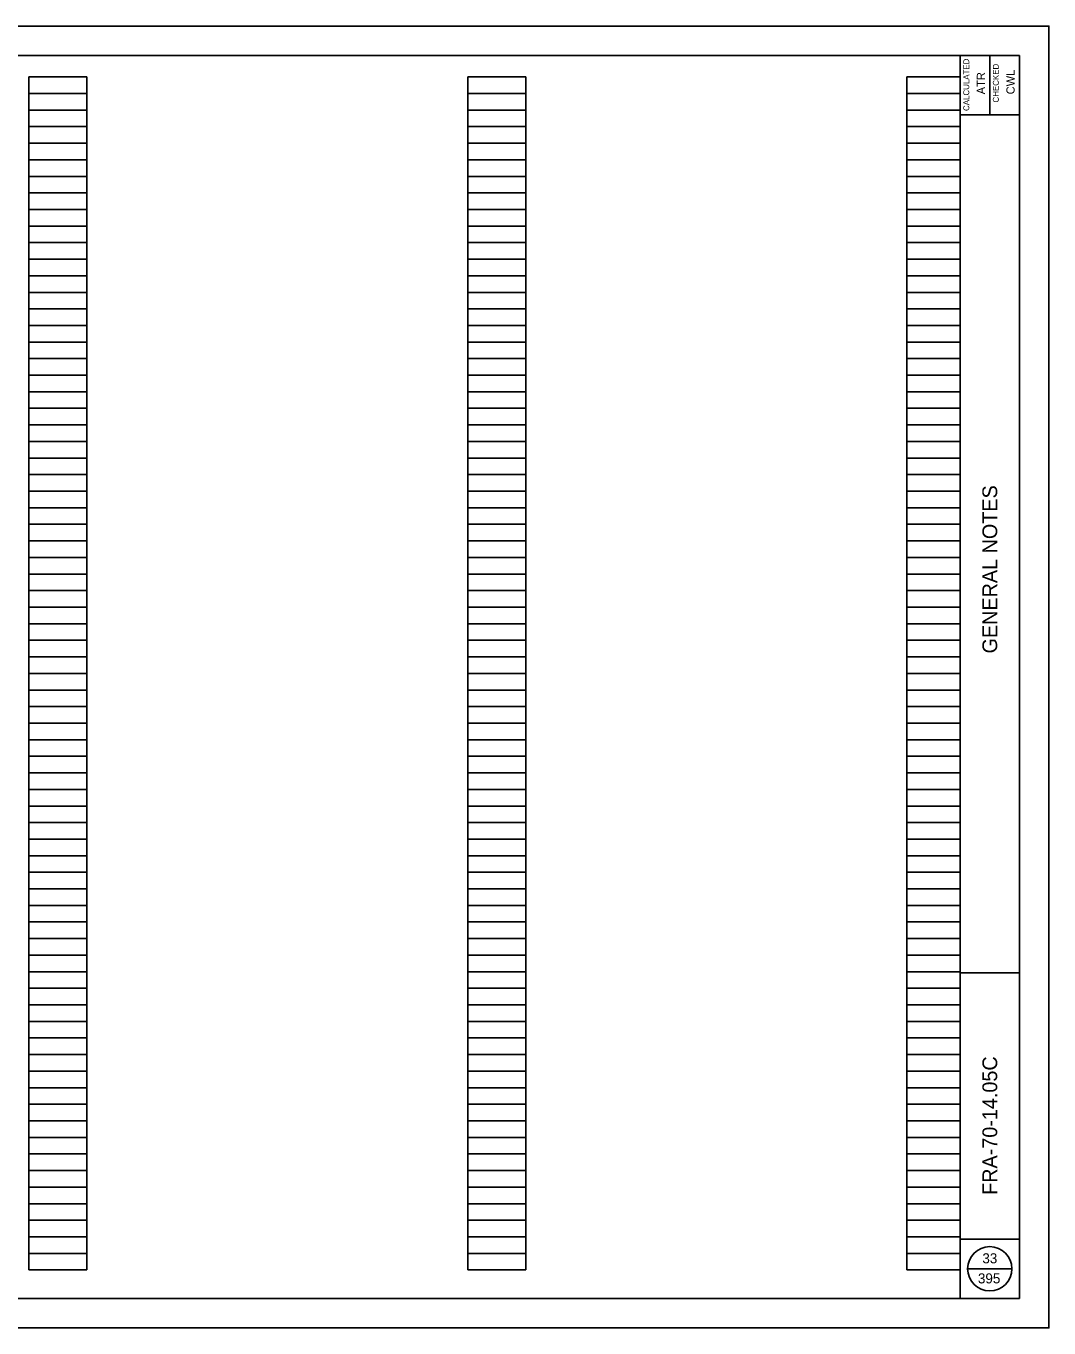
# Model space of a CAD drawing. Extents: x 0 to 34, y 0 to 22.
# Drawn here: x 16.71 to 34, y 0 to 22 of the extents above; entities that cross this region are included whole.
import ezdxf

# ---------------------------------------------------------------- set-up
doc = ezdxf.new("R2010")
doc.units = 0
for name, color, linetype in [('SC_Scratch1', 7, 'Continuous'), ('SH_Border', 7, 'Continuous'), ('SH_Cut_Line', 7, 'Continuous'), ('SH_Data', 7, 'Continuous')]:
    doc.layers.add(name, color=color, linetype=linetype)

msp = doc.modelspace()

# ---------------------------------------------------------------- linework, layer by layer
at = {"layer": 'SC_Scratch1'}
for p, q in [((16.76, 0.98), (16.76, 21.14)), ((16.76, 21.14), (17.74, 21.14)), ((17.74, 0.98), (17.74, 21.14)), ((24.18, 0.98), (24.18, 21.14)), ((24.18, 21.14), (25.16, 21.14)), ((25.16, 0.98), (25.16, 21.14)), ((31.6, 0.98), (31.6, 21.14)), ((31.6, 21.14), (32.5, 21.14)), ((32.5, 0.98), (32.5, 21.14)), ((16.76, 20.86), (17.74, 20.86)), ((24.18, 20.86), (25.16, 20.86)), ((31.6, 20.86), (32.5, 20.86)), ((16.76, 20.58), (17.74, 20.58)), ((24.18, 20.58), (25.16, 20.58)), ((31.6, 20.58), (32.5, 20.58)), ((16.76, 20.3), (17.74, 20.3)), ((24.18, 20.3), (25.16, 20.3)), ((31.6, 20.3), (32.5, 20.3)), ((16.76, 20.02), (17.74, 20.02)), ((24.18, 20.02), (25.16, 20.02)), ((31.6, 20.02), (32.5, 20.02)), ((16.76, 19.74), (17.74, 19.74)), ((24.18, 19.74), (25.16, 19.74)), ((31.6, 19.74), (32.5, 19.74)), ((16.76, 19.46), (17.74, 19.46)), ((24.18, 19.46), (25.16, 19.46)), ((31.6, 19.46), (32.5, 19.46)), ((16.76, 19.18), (17.74, 19.18)), ((24.18, 19.18), (25.16, 19.18)), ((31.6, 19.18), (32.5, 19.18)), ((16.76, 18.9), (17.74, 18.9)), ((24.18, 18.9), (25.16, 18.9)), ((31.6, 18.9), (32.5, 18.9)), ((16.76, 18.62), (17.74, 18.62)), ((24.18, 18.62), (25.16, 18.62)), ((31.6, 18.62), (32.5, 18.62)), ((16.76, 18.34), (17.74, 18.34)), ((24.18, 18.34), (25.16, 18.34)), ((31.6, 18.34), (32.5, 18.34)), ((16.76, 18.06), (17.74, 18.06)), ((24.18, 18.06), (25.16, 18.06)), ((31.6, 18.06), (32.5, 18.06)), ((16.76, 17.78), (17.74, 17.78)), ((24.18, 17.78), (25.16, 17.78)), ((31.6, 17.78), (32.5, 17.78)), ((16.76, 17.5), (17.74, 17.5)), ((24.18, 17.5), (25.16, 17.5)), ((31.6, 17.5), (32.5, 17.5)), ((16.76, 17.22), (17.74, 17.22)), ((24.18, 17.22), (25.16, 17.22)), ((31.6, 17.22), (32.5, 17.22)), ((16.76, 16.94), (17.74, 16.94)), ((24.18, 16.94), (25.16, 16.94)), ((31.6, 16.94), (32.5, 16.94)), ((16.76, 16.66), (17.74, 16.66)), ((24.18, 16.66), (25.16, 16.66)), ((31.6, 16.66), (32.5, 16.66)), ((16.76, 16.38), (17.74, 16.38)), ((24.18, 16.38), (25.16, 16.38)), ((31.6, 16.38), (32.5, 16.38)), ((16.76, 16.1), (17.74, 16.1)), ((24.18, 16.1), (25.16, 16.1)), ((31.6, 16.1), (32.5, 16.1)), ((16.76, 15.82), (17.74, 15.82)), ((24.18, 15.82), (25.16, 15.82)), ((31.6, 15.82), (32.5, 15.82)), ((16.76, 15.54), (17.74, 15.54)), ((24.18, 15.54), (25.16, 15.54)), ((31.6, 15.54), (32.5, 15.54)), ((16.76, 15.26), (17.74, 15.26)), ((24.18, 15.26), (25.16, 15.26)), ((31.6, 15.26), (32.5, 15.26)), ((16.76, 14.98), (17.74, 14.98)), ((24.18, 14.98), (25.16, 14.98)), ((31.6, 14.98), (32.5, 14.98)), ((16.76, 14.7), (17.74, 14.7)), ((24.18, 14.7), (25.16, 14.7)), ((31.6, 14.7), (32.5, 14.7)), ((16.76, 14.42), (17.74, 14.42)), ((24.18, 14.42), (25.16, 14.42)), ((31.6, 14.42), (32.5, 14.42)), ((16.76, 14.14), (17.74, 14.14)), ((24.18, 14.14), (25.16, 14.14)), ((31.6, 14.14), (32.5, 14.14)), ((16.76, 13.86), (17.74, 13.86)), ((24.18, 13.86), (25.16, 13.86)), ((31.6, 13.86), (32.5, 13.86)), ((16.76, 13.58), (17.74, 13.58)), ((24.18, 13.58), (25.16, 13.58)), ((31.6, 13.58), (32.5, 13.58)), ((16.76, 13.3), (17.74, 13.3)), ((24.18, 13.3), (25.16, 13.3)), ((31.6, 13.3), (32.5, 13.3)), ((16.76, 13.02), (17.74, 13.02)), ((24.18, 13.02), (25.16, 13.02)), ((31.6, 13.02), (32.5, 13.02)), ((16.76, 12.74), (17.74, 12.74)), ((24.18, 12.74), (25.16, 12.74)), ((31.6, 12.74), (32.5, 12.74)), ((16.76, 12.46), (17.74, 12.46)), ((24.18, 12.46), (25.16, 12.46)), ((31.6, 12.46), (32.5, 12.46)), ((16.76, 12.18), (17.74, 12.18)), ((24.18, 12.18), (25.16, 12.18)), ((31.6, 12.18), (32.5, 12.18)), ((16.76, 11.9), (17.74, 11.9)), ((24.18, 11.9), (25.16, 11.9)), ((31.6, 11.9), (32.5, 11.9)), ((16.76, 11.62), (17.74, 11.62)), ((24.18, 11.62), (25.16, 11.62)), ((31.6, 11.62), (32.5, 11.62)), ((16.76, 11.34), (17.74, 11.34)), ((24.18, 11.34), (25.16, 11.34)), ((31.6, 11.34), (32.5, 11.34)), ((16.76, 11.06), (17.74, 11.06)), ((24.18, 11.06), (25.16, 11.06)), ((31.6, 11.06), (32.5, 11.06)), ((16.76, 10.78), (17.74, 10.78)), ((24.18, 10.78), (25.16, 10.78)), ((31.6, 10.78), (32.5, 10.78)), ((16.76, 10.5), (17.74, 10.5)), ((24.18, 10.5), (25.16, 10.5)), ((31.6, 10.5), (32.5, 10.5)), ((16.76, 10.22), (17.74, 10.22)), ((24.18, 10.22), (25.16, 10.22)), ((31.6, 10.22), (32.5, 10.22)), ((16.76, 9.94), (17.74, 9.94)), ((24.18, 9.94), (25.16, 9.94)), ((31.6, 9.94), (32.5, 9.94)), ((16.76, 9.66), (17.74, 9.66)), ((24.18, 9.66), (25.16, 9.66)), ((31.6, 9.66), (32.5, 9.66)), ((16.76, 9.38), (17.74, 9.38)), ((24.18, 9.38), (25.16, 9.38)), ((31.6, 9.38), (32.5, 9.38)), ((16.76, 9.1), (17.74, 9.1)), ((24.18, 9.1), (25.16, 9.1)), ((31.6, 9.1), (32.5, 9.1)), ((16.76, 8.82), (17.74, 8.82)), ((24.18, 8.82), (25.16, 8.82)), ((31.6, 8.82), (32.5, 8.82)), ((16.76, 8.54), (17.74, 8.54)), ((24.18, 8.54), (25.16, 8.54)), ((31.6, 8.54), (32.5, 8.54)), ((16.76, 8.26), (17.74, 8.26)), ((24.18, 8.26), (25.16, 8.26)), ((31.6, 8.26), (32.5, 8.26)), ((16.76, 7.98), (17.74, 7.98)), ((24.18, 7.98), (25.16, 7.98)), ((31.6, 7.98), (32.5, 7.98)), ((16.76, 7.7), (17.74, 7.7)), ((24.18, 7.7), (25.16, 7.7)), ((31.6, 7.7), (32.5, 7.7)), ((16.76, 7.42), (17.74, 7.42)), ((24.18, 7.42), (25.16, 7.42)), ((31.6, 7.42), (32.5, 7.42)), ((16.76, 7.14), (17.74, 7.14)), ((24.18, 7.14), (25.16, 7.14)), ((31.6, 7.14), (32.5, 7.14)), ((16.76, 6.86), (17.74, 6.86)), ((24.18, 6.86), (25.16, 6.86)), ((31.6, 6.86), (32.5, 6.86)), ((16.76, 6.58), (17.74, 6.58)), ((24.18, 6.58), (25.16, 6.58)), ((31.6, 6.58), (32.5, 6.58)), ((16.76, 6.3), (17.74, 6.3)), ((24.18, 6.3), (25.16, 6.3)), ((31.6, 6.3), (32.5, 6.3)), ((16.76, 6.02), (17.74, 6.02)), ((24.18, 6.02), (25.16, 6.02)), ((31.6, 6.02), (32.5, 6.02)), ((16.76, 5.74), (17.74, 5.74)), ((24.18, 5.74), (25.16, 5.74)), ((31.6, 5.74), (32.5, 5.74)), ((16.76, 5.46), (17.74, 5.46)), ((24.18, 5.46), (25.16, 5.46)), ((31.6, 5.46), (32.5, 5.46)), ((16.76, 5.18), (17.74, 5.18)), ((24.18, 5.18), (25.16, 5.18)), ((31.6, 5.18), (32.5, 5.18)), ((16.76, 4.9), (17.74, 4.9)), ((24.18, 4.9), (25.16, 4.9)), ((31.6, 4.9), (32.5, 4.9)), ((16.76, 4.62), (17.74, 4.62)), ((24.18, 4.62), (25.16, 4.62)), ((31.6, 4.62), (32.5, 4.62)), ((16.76, 4.34), (17.74, 4.34)), ((24.18, 4.34), (25.16, 4.34)), ((31.6, 4.34), (32.5, 4.34)), ((16.76, 4.06), (17.74, 4.06)), ((24.18, 4.06), (25.16, 4.06)), ((31.6, 4.06), (32.5, 4.06)), ((16.76, 3.78), (17.74, 3.78)), ((24.18, 3.78), (25.16, 3.78)), ((31.6, 3.78), (32.5, 3.78)), ((16.76, 3.5), (17.74, 3.5)), ((24.18, 3.5), (25.16, 3.5)), ((31.6, 3.5), (32.5, 3.5)), ((16.76, 3.22), (17.74, 3.22)), ((24.18, 3.22), (25.16, 3.22)), ((31.6, 3.22), (32.5, 3.22)), ((16.76, 2.94), (17.74, 2.94)), ((24.18, 2.94), (25.16, 2.94)), ((31.6, 2.94), (32.5, 2.94)), ((16.76, 2.66), (17.74, 2.66)), ((24.18, 2.66), (25.16, 2.66)), ((31.6, 2.66), (32.5, 2.66)), ((16.76, 2.38), (17.74, 2.38)), ((24.18, 2.38), (25.16, 2.38)), ((31.6, 2.38), (32.5, 2.38)), ((16.76, 2.1), (17.74, 2.1)), ((24.18, 2.1), (25.16, 2.1)), ((31.6, 2.1), (32.5, 2.1)), ((16.76, 1.82), (17.74, 1.82)), ((24.18, 1.82), (25.16, 1.82)), ((31.6, 1.82), (32.5, 1.82)), ((16.76, 1.54), (17.74, 1.54)), ((24.18, 1.54), (25.16, 1.54)), ((31.6, 1.54), (32.5, 1.54)), ((16.76, 1.26), (17.74, 1.26)), ((24.18, 1.26), (25.16, 1.26)), ((31.6, 1.26), (32.5, 1.26)), ((16.76, 0.98), (17.74, 0.98)), ((24.18, 0.98), (25.16, 0.98)), ((31.6, 0.98), (32.5, 0.98))]:
    msp.add_line(p, q, dxfattribs=at)
at = {"layer": 'SH_Border'}
for p, q in [((32.5, 0.5), (32.5, 21.5)), ((33, 21.5), (33, 20.5)), ((32.5, 20.5), (33.5, 20.5)), ((32.5, 6), (33.5, 6)), ((32.5, 1.5), (33.5, 1.5))]:
    msp.add_line(p, q, dxfattribs=at)
msp.add_lwpolyline([(2, 21.5), (33.5, 21.5), (33.5, 0.5), (2, 0.5)], close=True, dxfattribs=at)
at = {"layer": 'SH_Cut_Line'}
msp.add_lwpolyline([(0, 0), (34, 0), (34, 22), (0, 22)], close=True, dxfattribs=at)
at = {"layer": 'SH_Data'}
msp.add_line((32.625, 1), (33.375, 1), dxfattribs=at)
msp.add_circle((33, 1), 0.375, dxfattribs=at)

# ---------------------------------------------------------------- texts
for s, height, p in [('CALCULATED', 0.1, (32.652, 20.565)), ('CHECKED', 0.1, (33.152, 20.708)), ('ATR', 0.14, (32.92, 20.846)), ('CWL', 0.14, (33.42, 20.846)), ('GENERAL NOTES', 0.25, (33.125, 11.398)), ('FRA-70-14.05C', 0.25, (33.125, 2.249))]:
    msp.add_text(s, height=height, rotation=90, dxfattribs=at).set_placement(p)
for s, p in [('33', (32.874, 1.092)), ('395', (32.799, 0.753))]:
    msp.add_text(s, height=0.17, dxfattribs=at).set_placement(p)

doc.saveas('drawing.dxf')
